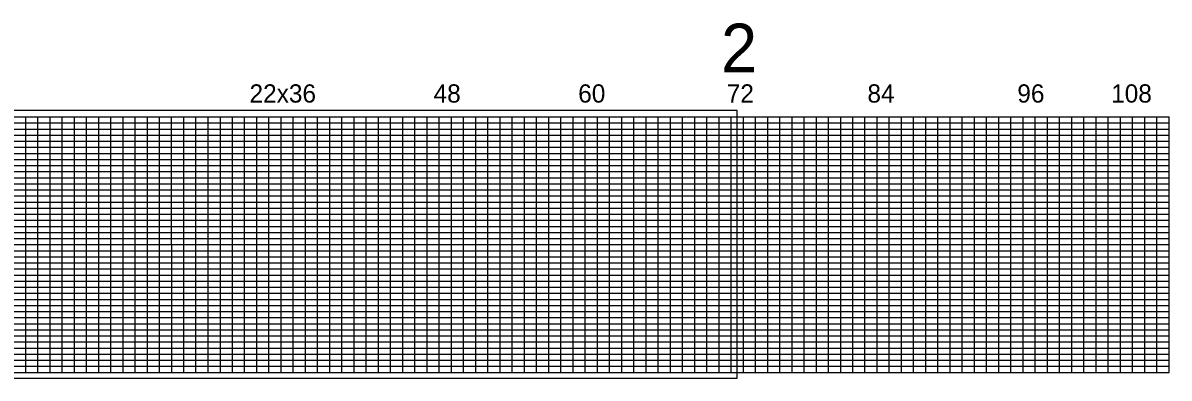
# Model space of a CAD drawing. Extents: x 1894907 to 1905782, y 740939 to 777025.
# Drawn here: x 1901070 to 1905782, y 775566 to 777025 of the extents above; entities that cross this region are included whole.
import ezdxf

# ---------------------------------------------------------------- set-up
doc = ezdxf.new("R2010")
doc.units = 0
for name, color, linetype in [('RD_PD_WallFill', 7, 'Continuous'), ('RD_SHT_IplotShp', 7, 'Continuous'), ('RD_Sketch8', 7, 'Continuous')]:
    doc.layers.add(name, color=color, linetype=linetype)

msp = doc.modelspace()

# ---------------------------------------------------------------- linework, layer by layer
at = {"layer": 'RD_PD_WallFill'}
for p, q in [((1900431.7, 776639.2), (1905781.6, 776639.2)), ((1900431.7, 776639.2), (1902181.7, 776639.2)), ((1900881.6, 776614.2), (1905781.6, 776614.2)), ((1900881.6, 776614.2), (1905781.6, 776614.2)), ((1901081.6, 775589.2), (1901081.7, 776639.2)), ((1901081.6, 775589.2), (1901081.7, 776639.2)), ((1901131.7, 775589.2), (1901131.6, 776639.2)), ((1901131.7, 775589.2), (1901131.6, 776639.2)), ((1901181.6, 775589.2), (1901181.7, 776639.2)), ((1901181.6, 775589.2), (1901181.7, 776639.2)), ((1901231.6, 775589.2), (1901231.6, 776639.2)), ((1901231.6, 775589.2), (1901231.6, 776639.2)), ((1901281.6, 775589.2), (1901281.6, 776639.2)), ((1901281.6, 775589.2), (1901281.6, 776639.2)), ((1901331.6, 775589.2), (1901331.6, 776639.2)), ((1901331.6, 775589.2), (1901331.6, 776639.2)), ((1901381.6, 775589.2), (1901381.6, 776639.2)), ((1901381.6, 775589.2), (1901381.6, 776639.2)), ((1901431.6, 775589.2), (1901431.6, 776639.2)), ((1901431.6, 775589.2), (1901431.6, 776639.2)), ((1901481.7, 775589.2), (1901481.6, 776639.2)), ((1901481.7, 775589.2), (1901481.6, 776639.2)), ((1901531.6, 775589.2), (1901531.7, 776639.2)), ((1901531.6, 775589.2), (1901531.7, 776639.2)), ((1901581.6, 775589.2), (1901581.6, 776639.2)), ((1901581.6, 775589.2), (1901581.6, 776639.2)), ((1901631.6, 775589.2), (1901631.6, 776639.2)), ((1901631.6, 775589.2), (1901631.6, 776639.2)), ((1901681.7, 775589.2), (1901681.6, 776639.2)), ((1901681.7, 775589.2), (1901681.6, 776639.2)), ((1901731.7, 775589.2), (1901731.7, 776639.2)), ((1901731.7, 775589.2), (1901731.7, 776639.2)), ((1901781.6, 775589.2), (1901781.6, 776639.2)), ((1901781.6, 775589.2), (1901781.6, 776639.2)), ((1901831.7, 775589.2), (1901831.6, 776639.2)), ((1901831.7, 775589.2), (1901831.6, 776639.2)), ((1901881.7, 775589.2), (1901881.7, 776639.2)), ((1901881.7, 775589.2), (1901881.7, 776639.2)), ((1901931.6, 775589.2), (1901931.7, 776639.2)), ((1901931.6, 775589.2), (1901931.7, 776639.2)), ((1901981.6, 775589.2), (1901981.6, 776639.2)), ((1901981.6, 775589.2), (1901981.6, 776639.2)), ((1902031.7, 775589.2), (1902031.7, 776639.2)), ((1902031.7, 775589.2), (1902031.7, 776639.2)), ((1902081.7, 775589.2), (1902081.7, 776639.2)), ((1902081.7, 775589.2), (1902081.7, 776639.2)), ((1902131.7, 775589.2), (1902131.7, 776639.2)), ((1902131.7, 775589.2), (1902131.7, 776639.2)), ((1902181.7, 775589.2), (1902181.7, 776639.2)), ((1902181.7, 775589.2), (1902181.7, 776639.2)), ((1902231.7, 775589.2), (1902231.7, 776639.2)), ((1902231.7, 775589.2), (1902231.7, 776639.2)), ((1902281.7, 775589.2), (1902281.7, 776639.2)), ((1902281.7, 775589.2), (1902281.7, 776639.2)), ((1902331.7, 775589.2), (1902331.7, 776639.2)), ((1902331.7, 775589.2), (1902331.7, 776639.2)), ((1902381.7, 775589.2), (1902381.7, 776639.2)), ((1902381.7, 775589.2), (1902381.7, 776639.2)), ((1902431.7, 775589.2), (1902431.7, 776639.2)), ((1902431.7, 775589.2), (1902431.7, 776639.2)), ((1902481.7, 775589.2), (1902481.7, 776639.2)), ((1902481.7, 775589.2), (1902481.7, 776639.2)), ((1902531.7, 775589.2), (1902531.7, 776639.2)), ((1902531.7, 775589.2), (1902531.7, 776639.2)), ((1902581.7, 775589.2), (1902581.7, 776639.2)), ((1902581.7, 775589.2), (1902581.7, 776639.2)), ((1902631.7, 775589.2), (1902631.7, 776639.2)), ((1902631.7, 775589.2), (1902631.7, 776639.2)), ((1902681.7, 775589.2), (1902681.7, 776639.2)), ((1902681.7, 775589.2), (1902681.7, 776639.2)), ((1902731.7, 775589.2), (1902731.7, 776639.2)), ((1902731.7, 775589.2), (1902731.7, 776639.2)), ((1902781.7, 775589.2), (1902781.7, 776639.2)), ((1902781.7, 775589.2), (1902781.7, 776639.2)), ((1902831.7, 775589.2), (1902831.7, 776639.2)), ((1902831.7, 775589.2), (1902831.7, 776639.2)), ((1902881.7, 775589.2), (1902881.7, 776639.2)), ((1902881.7, 775589.2), (1902881.7, 776639.2)), ((1902931.7, 775589.2), (1902931.7, 776639.2)), ((1902931.7, 775589.2), (1902931.7, 776639.2)), ((1902981.7, 775589.2), (1902981.7, 776639.2)), ((1902981.7, 775589.2), (1902981.7, 776639.2)), ((1903031.7, 775589.2), (1903031.7, 776639.2)), ((1903031.7, 775589.2), (1903031.7, 776639.2)), ((1903081.7, 775589.2), (1903081.7, 776639.2)), ((1903081.7, 775589.2), (1903081.7, 776639.2)), ((1903131.7, 775589.2), (1903131.7, 776639.2)), ((1903131.7, 775589.2), (1903131.7, 776639.2)), ((1903181.7, 775589.2), (1903181.7, 776639.2)), ((1903181.7, 775589.2), (1903181.7, 776639.2)), ((1903231.7, 775589.2), (1903231.7, 776639.2)), ((1903231.7, 775589.2), (1903231.7, 776639.2)), ((1903281.7, 775589.2), (1903281.7, 776639.2)), ((1903281.7, 775589.2), (1903281.7, 776639.2)), ((1903331.7, 775589.2), (1903331.7, 776639.2)), ((1903331.7, 775589.2), (1903331.7, 776639.2)), ((1903381.7, 775589.2), (1903381.7, 776639.2)), ((1903381.7, 775589.2), (1903381.7, 776639.2)), ((1903431.7, 775589.2), (1903431.7, 776639.2)), ((1903431.7, 775589.2), (1903431.7, 776639.2)), ((1903481.7, 775589.2), (1903481.7, 776639.2)), ((1903481.7, 775589.2), (1903481.7, 776639.2)), ((1903531.7, 775589.2), (1903531.7, 776639.2)), ((1903531.7, 775589.2), (1903531.7, 776639.2)), ((1903581.7, 775589.2), (1903581.7, 776639.2)), ((1903581.7, 775589.2), (1903581.7, 776639.2)), ((1903631.7, 775589.2), (1903631.7, 776639.2)), ((1903631.7, 775589.2), (1903631.7, 776639.2)), ((1903681.7, 775589.2), (1903681.7, 776639.2)), ((1903681.7, 775589.2), (1903681.7, 776639.2)), ((1903731.7, 775589.2), (1903731.7, 776639.2)), ((1903731.7, 775589.2), (1903731.7, 776639.2)), ((1903781.7, 775589.2), (1903781.7, 776639.2)), ((1903781.7, 775589.2), (1903781.7, 776639.2)), ((1903831.7, 775589.2), (1903831.7, 776639.2)), ((1903831.7, 775589.2), (1903831.7, 776639.2)), ((1903881.7, 775589.2), (1903881.7, 776639.2)), ((1903881.7, 775589.2), (1903881.7, 776639.2)), ((1903931.7, 775589.2), (1903931.7, 776639.2)), ((1903931.7, 775589.2), (1903931.7, 776639.2)), ((1903981.7, 775589.2), (1903981.7, 776639.2)), ((1903981.7, 775589.2), (1903981.7, 776639.2)), ((1904031.7, 775589.2), (1904031.7, 776639.2)), ((1904031.7, 775589.2), (1904031.7, 776639.2)), ((1904081.7, 775589.2), (1904081.7, 776639.2)), ((1904081.7, 775589.2), (1904081.7, 776639.2)), ((1904131.7, 775589.2), (1904131.7, 776639.2)), ((1904131.7, 775589.2), (1904131.7, 776639.2)), ((1904181.7, 775589.2), (1904181.7, 776639.2)), ((1904181.7, 775589.2), (1904181.7, 776639.2)), ((1904231.7, 775589.2), (1904231.7, 776639.2)), ((1904231.7, 775589.2), (1904231.7, 776639.2)), ((1904281.7, 775589.2), (1904281.7, 776639.2)), ((1904281.7, 775589.2), (1904281.7, 776639.2)), ((1904331.7, 775589.2), (1904331.7, 776639.2)), ((1904331.7, 775589.2), (1904331.7, 776639.2)), ((1904381.7, 775589.2), (1904381.7, 776639.2)), ((1904381.7, 775589.2), (1904381.7, 776639.2)), ((1904431.7, 775589.2), (1904431.7, 776639.2)), ((1904431.7, 775589.2), (1904431.7, 776639.2)), ((1904481.7, 775589.2), (1904481.7, 776639.2)), ((1904481.7, 775589.2), (1904481.7, 776639.2)), ((1904531.7, 775589.2), (1904531.7, 776639.2)), ((1904531.7, 775589.2), (1904531.7, 776639.2)), ((1904581.7, 775589.2), (1904581.7, 776639.2)), ((1904581.7, 775589.2), (1904581.7, 776639.2)), ((1904631.7, 775589.2), (1904631.7, 776639.2)), ((1904631.7, 775589.2), (1904631.7, 776639.2)), ((1904681.7, 775589.2), (1904681.7, 776639.2)), ((1904681.7, 775589.2), (1904681.7, 776639.2)), ((1904731.7, 775589.2), (1904731.7, 776639.2)), ((1904731.7, 775589.2), (1904731.7, 776639.2)), ((1904781.7, 775589.2), (1904781.7, 776639.2)), ((1904781.7, 775589.2), (1904781.7, 776639.2)), ((1904831.7, 775589.2), (1904831.7, 776639.2)), ((1904831.7, 775589.2), (1904831.7, 776639.2)), ((1904881.7, 775589.2), (1904881.7, 776639.2)), ((1904881.7, 775589.2), (1904881.7, 776639.2)), ((1904931.7, 775589.2), (1904931.7, 776639.2)), ((1904931.7, 775589.2), (1904931.7, 776639.2)), ((1904981.7, 775589.2), (1904981.7, 776639.2)), ((1904981.7, 775589.2), (1904981.7, 776639.2)), ((1905031.7, 775589.2), (1905031.7, 776639.2)), ((1905031.7, 775589.2), (1905031.7, 776639.2)), ((1905081.7, 775589.2), (1905081.7, 776639.2)), ((1905081.7, 775589.2), (1905081.7, 776639.2)), ((1905131.7, 775589.2), (1905131.7, 776639.2)), ((1905131.7, 775589.2), (1905131.7, 776639.2)), ((1905181.7, 775589.2), (1905181.7, 776639.2)), ((1905181.7, 775589.2), (1905181.7, 776639.2)), ((1905231.7, 775589.2), (1905231.7, 776639.2)), ((1905231.7, 775589.2), (1905231.7, 776639.2)), ((1905281.7, 775589.2), (1905281.7, 776639.2)), ((1905281.7, 775589.2), (1905281.7, 776639.2)), ((1905331.7, 775589.2), (1905331.7, 776639.2)), ((1905331.7, 775589.2), (1905331.7, 776639.2)), ((1905381.7, 775589.2), (1905381.7, 776639.2)), ((1905381.7, 775589.2), (1905381.7, 776639.2)), ((1905431.7, 775589.2), (1905431.7, 776639.2)), ((1905431.7, 775589.2), (1905431.7, 776639.2)), ((1905481.7, 775589.2), (1905481.7, 776639.2)), ((1905481.7, 775589.2), (1905481.7, 776639.2)), ((1905531.7, 775589.2), (1905531.7, 776639.2)), ((1905531.7, 775589.2), (1905531.7, 776639.2)), ((1905581.7, 775589.2), (1905581.7, 776639.2)), ((1905581.7, 775589.2), (1905581.7, 776639.2)), ((1905631.7, 775589.2), (1905631.7, 776639.2)), ((1905631.7, 775589.2), (1905631.7, 776639.2)), ((1905681.7, 775589.2), (1905681.7, 776639.2)), ((1905681.7, 775589.2), (1905681.7, 776639.2)), ((1905731.7, 775589.2), (1905731.7, 776639.2)), ((1905731.7, 775589.2), (1905731.7, 776639.2)), ((1905781.7, 775589.2), (1905781.7, 776639.2)), ((1905781.7, 775589.2), (1905781.7, 776639.2)), ((1900881.6, 776589.2), (1905781.6, 776589.2)), ((1900881.6, 776564.2), (1905781.6, 776564.2)), ((1900881.6, 776539.2), (1905781.6, 776539.2)), ((1900881.6, 776514.2), (1905781.6, 776514.2)), ((1900431.6, 776489.2), (1905781.6, 776489.2)), ((1900431.7, 776464.2), (1905781.6, 776464.2)), ((1900431.6, 776439.2), (1905781.6, 776439.2)), ((1900431.6, 776414.2), (1905781.6, 776414.2)), ((1900431.6, 776389.2), (1905781.6, 776389.2)), ((1900431.6, 776364.2), (1905781.6, 776364.2)), ((1900431.6, 776339.2), (1905781.6, 776339.2)), ((1900431.6, 776314.2), (1905781.6, 776314.2)), ((1900431.6, 776289.2), (1905781.6, 776289.2)), ((1900431.6, 776264.2), (1905781.6, 776264.2)), ((1900431.6, 776239.2), (1905781.6, 776239.2)), ((1900431.6, 776214.2), (1905781.6, 776214.2)), ((1900431.6, 776189.2), (1905781.6, 776189.2)), ((1900431.6, 776164.2), (1905781.6, 776164.2)), ((1900431.6, 776139.2), (1905781.6, 776139.2)), ((1900431.6, 776114.2), (1905781.6, 776114.2)), ((1900431.6, 776089.2), (1905781.6, 776089.2)), ((1900431.6, 776064.2), (1905781.6, 776064.2)), ((1900431.6, 776039.2), (1905781.6, 776039.2)), ((1900431.6, 776014.2), (1905781.6, 776014.2)), ((1900431.6, 775989.2), (1905781.6, 775989.2)), ((1900431.6, 775964.2), (1905781.6, 775964.2)), ((1900431.6, 775939.2), (1905781.6, 775939.2)), ((1900431.6, 775914.2), (1905781.6, 775914.2)), ((1900431.6, 775889.2), (1905781.6, 775889.2)), ((1900431.6, 775864.2), (1905781.6, 775864.2)), ((1900431.6, 775839.2), (1905781.6, 775839.2)), ((1900431.6, 775814.2), (1905781.6, 775814.2)), ((1900431.6, 775789.2), (1905781.6, 775789.2)), ((1900431.6, 775764.2), (1905781.6, 775764.2)), ((1900431.6, 775739.2), (1905781.6, 775739.2)), ((1900431.6, 775714.2), (1905781.6, 775714.2)), ((1900431.6, 775689.2), (1905781.6, 775689.2)), ((1900431.6, 775664.2), (1905781.6, 775664.2)), ((1900431.6, 775639.2), (1905781.6, 775639.2)), ((1900431.6, 775614.2), (1905781.6, 775614.2)), ((1900431.6, 775589.2), (1905781.6, 775589.2)), ((1900431.6, 775589.2), (1905781.6, 775589.2))]:
    msp.add_line(p, q, dxfattribs=at)
at = {"layer": 'RD_SHT_IplotShp'}
msp.add_lwpolyline([(1900406.7, 775565.6), (1904006.6, 775565.6), (1904006.6, 776665.6), (1900406.7, 776665.6)], close=True, dxfattribs=at)

# ---------------------------------------------------------------- texts
at = {"layer": 'RD_PD_WallFill'}
for s, p in [('22x36', (1902001.7, 776697.9)), ('22x36', (1902001.7, 776697.9)), ('48', (1902758.3, 776697.9)), ('48', (1902758.3, 776697.9)), ('60', (1903352.8, 776697.9)), ('60', (1903352.8, 776697.9)), ('72', (1903963.5, 776697.9)), ('72', (1903963.5, 776697.9)), ('84', (1904541.7, 776697.9)), ('84', (1904541.7, 776697.9)), ('96', (1905157.8, 776697.9)), ('96', (1905157.8, 776697.9)), ('108', (1905543.6, 776697.9))]:
    msp.add_text(s, height=75, dxfattribs=at).set_placement(p)
at = {"layer": 'RD_Sketch8'}
msp.add_text('2', height=200, dxfattribs=at).set_placement((1903939.8, 776822.3))

doc.saveas('drawing.dxf')
